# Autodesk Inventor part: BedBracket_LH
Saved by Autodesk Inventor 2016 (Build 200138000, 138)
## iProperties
Created: 2016-03
Part Number: BedBracket_LH
Material: Generic
Document SubType Name: Modeling
Designer: bongo_000
Density: 1 g/cm^3
Appearance: Default
Author: bongo_000
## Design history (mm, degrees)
feature "Base1"
body "Solid1"
